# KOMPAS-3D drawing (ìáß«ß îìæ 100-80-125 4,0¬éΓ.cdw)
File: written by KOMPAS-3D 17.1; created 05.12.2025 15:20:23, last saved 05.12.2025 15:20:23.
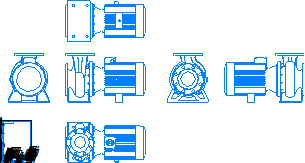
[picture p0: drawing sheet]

Sheet 1: A4, portrait

Title block, sheet 1: name: Насос МНС / 100-80-125 4,0кВт; material: Сталь 10  ГОСТ 1050-88; mass: 138,64; sheets: 1; sheet format: A4

Views: Проекционный вид 2, Проекционный вид 3, Проекционный вид 4, Проекционный вид 5, Проекционный вид 6
Referenced files in \\adlc.lan\data\АДЛ_ПКД\3D-модели\ADL production\Насосы ГРАНПАМП\Насосы ГРАНПАМП серии МНС\KOMPAS 3D\: Насос МНС 100-80-125_4,0.m3d
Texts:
  Andrey
  АДЛ
Dimensions and other numbers on the sheet: 1:1; 1; 100-80-125 4,0кВт; 138,64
